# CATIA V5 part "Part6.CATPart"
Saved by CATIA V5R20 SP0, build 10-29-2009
Part number: Part6
Bounding box of the stored display mesh (mm): x -25 to 25, y -50 to 50, z -1.5 to 32
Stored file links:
  E:\Ehsan\Catia\Tamrin\Digital Mockup\2\Part6.CATPart
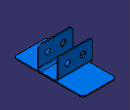
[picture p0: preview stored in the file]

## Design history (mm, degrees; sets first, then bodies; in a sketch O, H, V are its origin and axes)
Body1 (main body)
  Sketch1 on xy-plane, origin (0, 0, 0), H (1, 0, 0), V (0, 1, 0)
    line L1 (25, 15) -> (25, -15)
    line L2 (25, -15) -> (-25, -15)
    line L3 (-25, -15) -> (-25, 15)
    line L4 (-25, 15) -> (25, 15)
    distance L2 L4 = 30
    distance L1 L3 = 50
    vertical: L1 V, L3 V
    horizontal: L2 H, L4 H
    equidistance: L1 L3 O, L2 L4 O
  Pad1: profile Sketch1, direction (0, 0, 1), length 32
  Fillet1: radius 5, on edge [start face of Pad1 | face of Pad1 from Sketch1.L4]; edge [start face of Pad1 | face of Pad1 from Sketch1.L2]
  Shell1: IntOffset 1.5, Face (end face of Pad1; face of Pad1 from Sketch1.L1; face of Pad1 from Sketch1.L3), ExtOffset 0
  Sketch2 on face of Pad1 from Sketch1.L4, origin (0, 15, 0), H (-1, 0, 0), V (0, 0, 1)
    circle A1 centre (11, 18) radius 4
    point P1 (11, 18)
    circle A2 centre (-11, 18) radius 4
    distance P1 H = 18
    distance P1 V = 11
    radius A1 = 4
    symmetry: A1 A2 V
  Pocket1: profile Sketch2, direction (0, -1, 0), through (limit type 3)
  Fillet2: radius 5, on edge [face of Pad1 from Sketch1.L3 | end face of Pad1] (x2); edge [face of Pad1 from Sketch1.L1 | end face of Pad1] (x2)
  Sketch3 on start face of Pad1, origin (0, 0, 0), H (1, 0, 0), V (0, -1, 0)
    line L1 (0, -50) -> (0, 50)
    length L1 = 100
    midpoint: L1 O
    vertical: L1 V
  Pad2: profile Sketch3, direction (0, 0, -1), length 1.5, thin wall 48
  Fillet3: radius 5, on edge [face of Pad2 | face of Pad2] (x4)
  Point1: type OnPlane, Support end face of Pad2, H 18.072, V 32.955, Direction (1, 0, 0)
